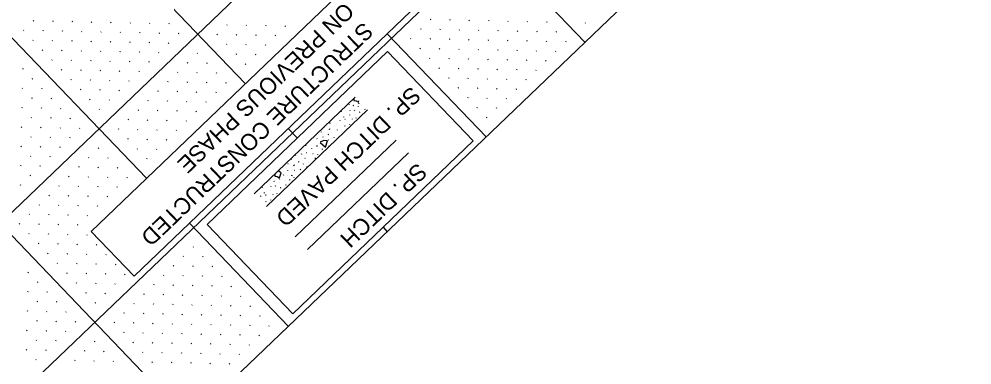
# Model space of a CAD drawing. Extents: x 2148987 to 2151117, y 142806 to 144993.
# Drawn here: x 2149870.3 to 2150218.3, y 143765.8 to 143892.2 of the extents above; entities that cross this region are included whole.
import ezdxf

# ---------------------------------------------------------------- set-up
doc = ezdxf.new("R2010")
doc.units = 0
for name, color, linetype in [('PR_Grading_Txt', 7, 'Continuous'), ('PR_Misc_Improvement', 7, 'Continuous'), ('PR_PIER_PH3', 7, 'Continuous'), ('PR_Road_Concrete', 7, 'Continuous'), ('PR_Storm_Ditch_Paved', 7, 'Continuous'), ('PR_Storm_Ditch_Special', 7, 'Continuous'), ('SHT_Profile_Grid_Minor', 7, 'Continuous')]:
    doc.layers.add(name, color=color, linetype=linetype)

msp = doc.modelspace()

# ---------------------------------------------------------------- linework, layer by layer
at = {"layer": 'PR_Misc_Improvement'}
for points in [[(2150024.95, 143906.21), (2149912.27, 143798.22), (2149896.58, 143814.59), (2150009.26, 143922.58)], [(2150036.16, 143847.7), (2149970.24, 143784.53), (2149938.95, 143817.18), (2150004.87, 143880.35)]]:
    msp.add_lwpolyline(points, close=True, dxfattribs=at)
at = {"layer": 'PR_PIER_PH3'}
for p, q in [((2150504.13, 144431.57), (2149367, 143341.82)), ((2150538.73, 144395.47), (2149401.59, 143305.72)), ((2149731, 144244.68), (2150076.96, 143883.69)), ((2149658.8, 144175.49), (2149952.92, 143868.59)), ((2149622.71, 144140.89), (2149916.82, 143833.99)), ((2149622.71, 144140.89), (2149916.82, 143833.99)), ((2149586.61, 144106.3), (2149932.56, 143745.3)), ((2150004.71, 143886.81), (2150040.86, 143849.09)), ((2149968.61, 143852.22), (2149971.91, 143848.77)), ((2149932.51, 143817.62), (2149968.66, 143779.9)), ((2149932.51, 143817.62), (2149968.66, 143779.9)), ((2150003.2, 143816.12), (2150004.76, 143814.49))]:
    msp.add_line(p, q, dxfattribs=at)
at = {"layer": 'PR_Road_Concrete'}
msp.add_line((2150573.32, 144359.37), (2149436.19, 143269.62), dxfattribs=at)
at = {"layer": 'PR_Storm_Ditch_Paved'}
for p, q in [((2149992.57, 143862.54), (2149992.42, 143862.55)), ((2149987.92, 143858.46), (2149987.92, 143858.31)), ((2149989.35, 143860.14), (2149989.33, 143860.16)), ((2149990.95, 143860.84), (2149990.95, 143860.92)), ((2149991.14, 143858.82), (2149991.14, 143858.67)), ((2149992.49, 143860.42), (2149992.34, 143860.65)), ((2149992.92, 143858.63), (2149992.77, 143858.86)), ((2149994.22, 143860.11), (2149994.23, 143860.19)), ((2149994.44, 143861.23), (2149994.29, 143861.46)), ((2149996.72, 143859.01), (2149996.57, 143859.25)), ((2149986.26, 143856.8), (2149986.26, 143856.87)), ((2149987.39, 143855.22), (2149987.38, 143855.07)), ((2149988.73, 143856.43), (2149988.73, 143856.28)), ((2149989.37, 143855.53), (2149989.21, 143855.53)), ((2149991.14, 143857.08), (2149991.14, 143857.16)), ((2149991.89, 143855.75), (2149991.89, 143855.59)), ((2149993.4, 143855.99), (2149993.4, 143856.06)), ((2149994.72, 143858.16), (2149994.53, 143858.05)), ((2149995.32, 143857.07), (2149995.32, 143856.91)), ((2149981.91, 143852.63), (2149981.72, 143852.75)), ((2149983.68, 143852.13), (2149983.52, 143851.74)), ((2149983.8, 143854.22), (2149983.8, 143854.06)), ((2149986.39, 143853.74), (2149986.39, 143853.81)), ((2149986.42, 143851.72), (2149986.42, 143851.57)), ((2149989.39, 143852.98), (2149989.24, 143853.21)), ((2149991.07, 143853.67), (2149991.07, 143853.75)), ((2149979.15, 143848.39), (2149979, 143848.55)), ((2149979.23, 143850.36), (2149979.11, 143850.37)), ((2149980.79, 143850.87), (2149980.79, 143850.95)), ((2149981.26, 143849.12), (2149981.25, 143848.97)), ((2149983.44, 143849.93), (2149983.17, 143849.97)), ((2149983.32, 143847.92), (2149983.17, 143847.92)), ((2149985.32, 143848.92), (2149985.32, 143849)), ((2149987.96, 143851.07), (2149987.96, 143851.15)), ((2149974.88, 143846.05), (2149974.88, 143845.89)), ((2149977.1, 143844.91), (2149977.06, 143844.8)), ((2149978.87, 143845.84), (2149979.25, 143845.84)), ((2149981.01, 143844.72), (2149981.01, 143844.56)), ((2149983.46, 143845.63), (2149983.31, 143845.63)), ((2149969.78, 143840.85), (2149969.62, 143840.85)), ((2149971.4, 143842.48), (2149971.21, 143842.37)), ((2149973.54, 143842.71), (2149973.39, 143842.94)), ((2149974.82, 143841.21), (2149974.66, 143841.21)), ((2149975.36, 143843.25), (2149975.21, 143843.25)), ((2149977.69, 143842.98), (2149977.61, 143842.99)), ((2149978.61, 143841.28), (2149978.34, 143841.25)), ((2149979.38, 143842.62), (2149979.38, 143842.7)), ((2149968.58, 143839.33), (2149968.43, 143839.33)), ((2149970.5, 143838.59), (2149970.82, 143838.89)), ((2149972.32, 143840.1), (2149972.31, 143839.95)), ((2149974.04, 143839.33), (2149974.04, 143839.17)), ((2149975.45, 143838.02), (2149975.29, 143838.02)), ((2149976.02, 143839.64), (2149976.02, 143839.71)), ((2149963.69, 143834.87), (2149963.54, 143834.87)), ((2149966.99, 143835.07), (2149966.84, 143835.3)), ((2149968.23, 143835.12), (2149968.23, 143835.19)), ((2149968.3, 143837.01), (2149968.3, 143836.86)), ((2149969.92, 143834.85), (2149969.97, 143835.27)), ((2149970.85, 143836.8), (2149970.7, 143836.81)), ((2149970.8, 143834.17), (2149970.8, 143834.25)), ((2149973.14, 143837.1), (2149972.95, 143837.3)), ((2149959.04, 143830.79), (2149959.04, 143830.63)), ((2149960.47, 143832.46), (2149960.45, 143832.49)), ((2149962.07, 143833.16), (2149962.07, 143833.24)), ((2149962.26, 143831.15), (2149962.26, 143830.99)), ((2149963.61, 143832.74), (2149963.46, 143832.97)), ((2149964.04, 143830.95), (2149963.89, 143831.19)), ((2149965.35, 143832.43), (2149965.35, 143832.51)), ((2149965.56, 143833.55), (2149965.41, 143833.78)), ((2149965.84, 143830.49), (2149965.65, 143830.38)), ((2149967.64, 143833.27), (2149967.64, 143833.35)), ((2149967.84, 143831.34), (2149967.69, 143831.57)), ((2149969.08, 143833.51), (2149969.08, 143833.36)), ((2149957.38, 143829.12), (2149957.38, 143829.2)), ((2149958.51, 143827.55), (2149958.5, 143827.39)), ((2149959.85, 143828.76), (2149959.85, 143828.6)), ((2149960.49, 143827.85), (2149960.33, 143827.86)), ((2149962.26, 143829.4), (2149962.26, 143829.48)), ((2149963.01, 143828.07), (2149963.01, 143827.92)), ((2149964.52, 143828.31), (2149964.52, 143828.39)), ((2149966.44, 143829.39), (2149966.44, 143829.24)), ((2149960.51, 143825.3), (2149960.36, 143825.53)), ((2149962.19, 143826), (2149962.19, 143826.08))]:
    msp.add_line(p, q, dxfattribs=at)
for points in [[(2149992.59, 143863.28), (2149992.58, 143862.45), (2149993.4, 143862.28), (2149994.21, 143861.81), (2149994.36, 143862.25)], [(2149980.31, 143847.14), (2149982.21, 143845.41), (2149982.97, 143847.72), (2149981.64, 143847.79), (2149980.31, 143847.17)], [(2149963.71, 143835.61), (2149963.7, 143834.78), (2149964.52, 143834.6), (2149965.33, 143834.13), (2149965.48, 143834.58)], [(2149965.48, 143834.58), (2149965.98, 143836.04), (2149964.97, 143836.75), (2149964.87, 143836.72)]]:
    msp.add_lwpolyline(points, dxfattribs=at)
at = {"layer": 'PR_Storm_Ditch_Special'}
for p, q in [((2149993, 143863.68), (2149956.12, 143828.34)), ((2149997.49, 143858.99), (2149960.61, 143823.65)), ((2150008.05, 143847.97), (2149971.17, 143812.63)), ((2150012.54, 143843.29), (2149975.66, 143807.95))]:
    msp.add_line(p, q, dxfattribs=at)
at = {"layer": 'SHT_Profile_Grid_Minor'}
for p, q in [((2149875.64, 143891.59), (2149875.46, 143891.42)), ((2149882.71, 143891.44), (2149882.53, 143891.27)), ((2149889.78, 143891.29), (2149889.6, 143891.12)), ((2149896.85, 143891.14), (2149896.67, 143890.97)), ((2149903.92, 143890.99), (2149903.74, 143890.82)), ((2149910.99, 143890.84), (2149910.81, 143890.67)), ((2149918.06, 143890.69), (2149917.88, 143890.52)), ((2149925.13, 143890.54), (2149924.95, 143890.37)), ((2149946.34, 143890.09), (2149946.15, 143889.92)), ((2149953.4, 143889.94), (2149953.22, 143889.77)), ((2149960.47, 143889.79), (2149960.29, 143889.62)), ((2149967.54, 143889.64), (2149967.36, 143889.47)), ((2150020.64, 143892.04), (2150020.46, 143891.87)), ((2150027.71, 143891.89), (2150027.53, 143891.72)), ((2150034.78, 143891.74), (2150034.6, 143891.57)), ((2150041.85, 143891.59), (2150041.67, 143891.42)), ((2150048.92, 143891.44), (2150048.74, 143891.27)), ((2150055.99, 143891.29), (2150055.81, 143891.12)), ((2150063.06, 143891.14), (2150062.88, 143890.97)), ((2150077.2, 143890.84), (2150077.02, 143890.67)), ((2149872.03, 143888.13), (2149871.85, 143887.96)), ((2149879.1, 143887.98), (2149878.92, 143887.81)), ((2149886.17, 143887.83), (2149885.99, 143887.66)), ((2149893.24, 143887.68), (2149893.06, 143887.51)), ((2149900.31, 143887.53), (2149900.13, 143887.36)), ((2149907.38, 143887.38), (2149907.2, 143887.21)), ((2149914.45, 143887.23), (2149914.27, 143887.06)), ((2149921.52, 143887.08), (2149921.34, 143886.91)), ((2149928.59, 143886.93), (2149928.41, 143886.76)), ((2149942.73, 143886.63), (2149942.54, 143886.46)), ((2149949.79, 143886.48), (2149949.61, 143886.31)), ((2149956.86, 143886.33), (2149956.68, 143886.16)), ((2149963.93, 143886.18), (2149963.75, 143886.01)), ((2150017.03, 143888.59), (2150016.85, 143888.41)), ((2150024.1, 143888.43), (2150023.92, 143888.26)), ((2150031.17, 143888.28), (2150030.99, 143888.11)), ((2150038.24, 143888.13), (2150038.06, 143887.96)), ((2150045.31, 143887.98), (2150045.13, 143887.81)), ((2150052.38, 143887.83), (2150052.2, 143887.66)), ((2150059.45, 143887.68), (2150059.27, 143887.51)), ((2150066.52, 143887.53), (2150066.34, 143887.36)), ((2149875.49, 143884.52), (2149875.31, 143884.35)), ((2149882.56, 143884.37), (2149882.38, 143884.2)), ((2149889.63, 143884.22), (2149889.45, 143884.05)), ((2149896.7, 143884.07), (2149896.52, 143883.9)), ((2149903.77, 143883.92), (2149903.59, 143883.75)), ((2149910.84, 143883.77), (2149910.66, 143883.6)), ((2149917.91, 143883.62), (2149917.73, 143883.45)), ((2149924.98, 143883.47), (2149924.8, 143883.3)), ((2149946.18, 143883.02), (2149946, 143882.85)), ((2149953.25, 143882.87), (2149953.07, 143882.7)), ((2149960.32, 143882.72), (2149960.14, 143882.55)), ((2150013.42, 143885.13), (2150013.24, 143884.95)), ((2150020.49, 143884.98), (2150020.31, 143884.8)), ((2150027.56, 143884.82), (2150027.38, 143884.65)), ((2150034.63, 143884.67), (2150034.45, 143884.5)), ((2150041.7, 143884.52), (2150041.52, 143884.35)), ((2150048.77, 143884.37), (2150048.59, 143884.2)), ((2150055.84, 143884.22), (2150055.66, 143884.05)), ((2150062.91, 143884.07), (2150062.73, 143883.9)), ((2150069.98, 143883.92), (2150069.8, 143883.75)), ((2149878.95, 143880.91), (2149878.77, 143880.74)), ((2149886.02, 143880.76), (2149885.84, 143880.59)), ((2149893.09, 143880.61), (2149892.91, 143880.44)), ((2149900.16, 143880.46), (2149899.98, 143880.29)), ((2149907.23, 143880.31), (2149907.05, 143880.14)), ((2149914.3, 143880.16), (2149914.12, 143879.99)), ((2149921.37, 143880.01), (2149921.19, 143879.84)), ((2149935.51, 143879.71), (2149935.32, 143879.54)), ((2149949.64, 143879.41), (2149949.46, 143879.24)), ((2149956.71, 143879.26), (2149956.53, 143879.09)), ((2150016.88, 143881.52), (2150016.7, 143881.34)), ((2150023.95, 143881.37), (2150023.77, 143881.19)), ((2150031.02, 143881.21), (2150030.84, 143881.04)), ((2150038.09, 143881.06), (2150037.91, 143880.89)), ((2150045.16, 143880.91), (2150044.98, 143880.74)), ((2150052.23, 143880.76), (2150052.05, 143880.59)), ((2150059.3, 143880.61), (2150059.12, 143880.44)), ((2150066.37, 143880.46), (2150066.19, 143880.29)), ((2149882.41, 143877.3), (2149882.23, 143877.13)), ((2149889.48, 143877.15), (2149889.3, 143876.98)), ((2149896.55, 143877), (2149896.37, 143876.83)), ((2149903.62, 143876.85), (2149903.44, 143876.68)), ((2149910.69, 143876.7), (2149910.51, 143876.53)), ((2149917.76, 143876.55), (2149917.58, 143876.38)), ((2149931.9, 143876.25), (2149931.72, 143876.08)), ((2149938.97, 143876.1), (2149938.78, 143875.93)), ((2149953.1, 143875.8), (2149952.92, 143875.63)), ((2150020.34, 143877.91), (2150020.16, 143877.73)), ((2150027.41, 143877.76), (2150027.23, 143877.58)), ((2150034.48, 143877.6), (2150034.3, 143877.43)), ((2150041.55, 143877.45), (2150041.37, 143877.28)), ((2150048.62, 143877.3), (2150048.44, 143877.13)), ((2150055.69, 143877.15), (2150055.51, 143876.98)), ((2150062.76, 143877), (2150062.58, 143876.83)), ((2149871.73, 143874), (2149871.55, 143873.82)), ((2149885.87, 143873.69), (2149885.69, 143873.52)), ((2149892.94, 143873.54), (2149892.76, 143873.37)), ((2149900.01, 143873.39), (2149899.83, 143873.22)), ((2149907.08, 143873.24), (2149906.9, 143873.07)), ((2149914.15, 143873.09), (2149913.97, 143872.92)), ((2149928.29, 143872.79), (2149928.11, 143872.62)), ((2149935.36, 143872.64), (2149935.17, 143872.47)), ((2149942.42, 143872.49), (2149942.24, 143872.32)), ((2150023.8, 143874.3), (2150023.62, 143874.12)), ((2150030.87, 143874.15), (2150030.69, 143873.97)), ((2150037.94, 143873.99), (2150037.76, 143873.82)), ((2150045.01, 143873.84), (2150044.83, 143873.67)), ((2150052.08, 143873.69), (2150051.9, 143873.52)), ((2150059.15, 143873.54), (2150058.97, 143873.37)), ((2149875.19, 143870.39), (2149875.01, 143870.21)), ((2149889.33, 143870.08), (2149889.15, 143869.91)), ((2149896.4, 143869.93), (2149896.22, 143869.76)), ((2149903.47, 143869.78), (2149903.29, 143869.61)), ((2149910.54, 143869.63), (2149910.36, 143869.46)), ((2149924.68, 143869.33), (2149924.5, 143869.16)), ((2149931.75, 143869.18), (2149931.56, 143869.01)), ((2149938.81, 143869.03), (2149938.63, 143868.86)), ((2149945.88, 143868.88), (2149945.7, 143868.71)), ((2150027.26, 143870.69), (2150027.08, 143870.51)), ((2150034.33, 143870.54), (2150034.15, 143870.36)), ((2150041.4, 143870.38), (2150041.22, 143870.21)), ((2150048.47, 143870.23), (2150048.29, 143870.06)), ((2150055.54, 143870.08), (2150055.36, 143869.91)), ((2149871.58, 143866.93), (2149871.4, 143866.75)), ((2149878.65, 143866.78), (2149878.47, 143866.6)), ((2149892.79, 143866.47), (2149892.61, 143866.3)), ((2149899.86, 143866.32), (2149899.68, 143866.15)), ((2149906.93, 143866.17), (2149906.75, 143866)), ((2149921.07, 143865.87), (2149920.89, 143865.7)), ((2149928.14, 143865.72), (2149927.95, 143865.55)), ((2149935.2, 143865.57), (2149935.02, 143865.4)), ((2149942.27, 143865.42), (2149942.09, 143865.25)), ((2150030.72, 143867.08), (2150030.54, 143866.9)), ((2150037.79, 143866.93), (2150037.61, 143866.75)), ((2150044.86, 143866.78), (2150044.68, 143866.6)), ((2150051.93, 143866.62), (2150051.75, 143866.45)), ((2149875.04, 143863.32), (2149874.86, 143863.14)), ((2149882.11, 143863.17), (2149881.93, 143862.99)), ((2149896.25, 143862.86), (2149896.07, 143862.69)), ((2149903.32, 143862.71), (2149903.14, 143862.54)), ((2149917.46, 143862.41), (2149917.28, 143862.24)), ((2149924.53, 143862.26), (2149924.34, 143862.09)), ((2149931.59, 143862.11), (2149931.41, 143861.94)), ((2149938.66, 143861.96), (2149938.48, 143861.79)), ((2150034.18, 143863.47), (2150034, 143863.29)), ((2150041.25, 143863.32), (2150041.07, 143863.14)), ((2150048.32, 143863.17), (2150048.14, 143862.99)), ((2149871.43, 143859.86), (2149871.25, 143859.68)), ((2149878.5, 143859.71), (2149878.32, 143859.53)), ((2149885.57, 143859.56), (2149885.39, 143859.38)), ((2149899.71, 143859.25), (2149899.53, 143859.08)), ((2149913.85, 143858.95), (2149913.67, 143858.78)), ((2149920.92, 143858.8), (2149920.73, 143858.63)), ((2149927.98, 143858.65), (2149927.8, 143858.48)), ((2149935.05, 143858.5), (2149934.87, 143858.33)), ((2150037.64, 143859.86), (2150037.46, 143859.68)), ((2150044.71, 143859.71), (2150044.53, 143859.53)), ((2149874.89, 143856.25), (2149874.71, 143856.07)), ((2149881.96, 143856.1), (2149881.78, 143855.92)), ((2149889.03, 143855.95), (2149888.85, 143855.77)), ((2149910.24, 143855.49), (2149910.06, 143855.32)), ((2149917.31, 143855.34), (2149917.12, 143855.17)), ((2149924.37, 143855.19), (2149924.19, 143855.02)), ((2149931.44, 143855.04), (2149931.26, 143854.87)), ((2150041.1, 143856.25), (2150040.92, 143856.07)), ((2149871.28, 143852.79), (2149871.1, 143852.61)), ((2149878.35, 143852.64), (2149878.17, 143852.46)), ((2149885.42, 143852.49), (2149885.24, 143852.31)), ((2149892.49, 143852.34), (2149892.31, 143852.16)), ((2149906.63, 143852.03), (2149906.45, 143851.86)), ((2149913.7, 143851.88), (2149913.51, 143851.71)), ((2149920.76, 143851.73), (2149920.58, 143851.56)), ((2149927.83, 143851.58), (2149927.65, 143851.41)), ((2149874.74, 143849.18), (2149874.56, 143849)), ((2149881.81, 143849.03), (2149881.63, 143848.85)), ((2149888.88, 143848.88), (2149888.7, 143848.7)), ((2149910.09, 143848.42), (2149909.9, 143848.25)), ((2149917.15, 143848.27), (2149916.97, 143848.1)), ((2149924.22, 143848.12), (2149924.04, 143847.95)), ((2149871.13, 143845.72), (2149870.95, 143845.54)), ((2149878.2, 143845.57), (2149878.02, 143845.39)), ((2149885.27, 143845.42), (2149885.09, 143845.24)), ((2149899.41, 143845.12), (2149899.23, 143844.94)), ((2149913.54, 143844.81), (2149913.36, 143844.64)), ((2149920.61, 143844.66), (2149920.43, 143844.49)), ((2149874.59, 143842.11), (2149874.41, 143841.93)), ((2149881.66, 143841.96), (2149881.48, 143841.78)), ((2149895.8, 143841.66), (2149895.62, 143841.48)), ((2149902.87, 143841.51), (2149902.68, 143841.33)), ((2149917, 143841.2), (2149916.82, 143841.03)), ((2149870.98, 143838.65), (2149870.8, 143838.48)), ((2149878.05, 143838.5), (2149877.87, 143838.32)), ((2149892.19, 143838.2), (2149892.01, 143838.02)), ((2149899.26, 143838.05), (2149899.08, 143837.87)), ((2149906.32, 143837.9), (2149906.14, 143837.72)), ((2149874.44, 143835.04), (2149874.26, 143834.87)), ((2149888.58, 143834.74), (2149888.4, 143834.56)), ((2149895.65, 143834.59), (2149895.47, 143834.41)), ((2149902.72, 143834.44), (2149902.53, 143834.26)), ((2149909.78, 143834.29), (2149909.6, 143834.11)), ((2149870.83, 143831.58), (2149870.65, 143831.41)), ((2149884.97, 143831.28), (2149884.79, 143831.1)), ((2149892.04, 143831.13), (2149891.86, 143830.95)), ((2149899.11, 143830.98), (2149898.92, 143830.8)), ((2149906.17, 143830.83), (2149905.99, 143830.65)), ((2149881.36, 143827.82), (2149881.18, 143827.65)), ((2149888.43, 143827.67), (2149888.25, 143827.49)), ((2149895.5, 143827.52), (2149895.31, 143827.34)), ((2149902.56, 143827.37), (2149902.38, 143827.19)), ((2149877.75, 143824.36), (2149877.57, 143824.19)), ((2149884.82, 143824.21), (2149884.64, 143824.04)), ((2149891.89, 143824.06), (2149891.7, 143823.88)), ((2149898.95, 143823.91), (2149898.77, 143823.73)), ((2149874.14, 143820.9), (2149873.96, 143820.73)), ((2149881.21, 143820.75), (2149881.03, 143820.58)), ((2149888.28, 143820.6), (2149888.09, 143820.43)), ((2149895.34, 143820.45), (2149895.16, 143820.27)), ((2149870.53, 143817.44), (2149870.35, 143817.27)), ((2149877.6, 143817.29), (2149877.42, 143817.12)), ((2149884.67, 143817.14), (2149884.48, 143816.97)), ((2149891.73, 143816.99), (2149891.55, 143816.82)), ((2149873.99, 143813.83), (2149873.81, 143813.66)), ((2149881.06, 143813.68), (2149880.87, 143813.51)), ((2149888.12, 143813.53), (2149887.94, 143813.36)), ((2149895.19, 143813.38), (2149895.01, 143813.21)), ((2149877.45, 143810.22), (2149877.26, 143810.05)), ((2149884.51, 143810.07), (2149884.33, 143809.9)), ((2149891.58, 143809.92), (2149891.4, 143809.75)), ((2149898.65, 143809.77), (2149898.47, 143809.6)), ((2149880.9, 143806.61), (2149880.72, 143806.44)), ((2149887.97, 143806.46), (2149887.79, 143806.29)), ((2149895.04, 143806.31), (2149894.86, 143806.14)), ((2149902.11, 143806.16), (2149901.93, 143805.99)), ((2149934, 143809.02), (2149933.82, 143808.84)), ((2149884.36, 143803), (2149884.18, 143802.83)), ((2149891.43, 143802.85), (2149891.25, 143802.68)), ((2149898.5, 143802.7), (2149898.32, 143802.53)), ((2149905.57, 143802.55), (2149905.39, 143802.38)), ((2149930.39, 143805.56), (2149930.21, 143805.38)), ((2149937.46, 143805.41), (2149937.28, 143805.23)), ((2149873.68, 143799.69), (2149873.5, 143799.52)), ((2149887.82, 143799.39), (2149887.64, 143799.22)), ((2149894.89, 143799.24), (2149894.71, 143799.07)), ((2149901.96, 143799.09), (2149901.78, 143798.92)), ((2149926.78, 143802.1), (2149926.6, 143801.92)), ((2149933.85, 143801.95), (2149933.67, 143801.77)), ((2149940.92, 143801.8), (2149940.74, 143801.62)), ((2149877.14, 143796.08), (2149876.96, 143795.91)), ((2149891.28, 143795.78), (2149891.1, 143795.61)), ((2149898.35, 143795.63), (2149898.17, 143795.46)), ((2149909.03, 143798.94), (2149908.85, 143798.77)), ((2149923.17, 143798.64), (2149922.99, 143798.46)), ((2149930.24, 143798.49), (2149930.06, 143798.31)), ((2149937.31, 143798.34), (2149937.13, 143798.16)), ((2149944.38, 143798.19), (2149944.2, 143798.01)), ((2149873.53, 143792.62), (2149873.35, 143792.45)), ((2149880.6, 143792.47), (2149880.42, 143792.3)), ((2149894.74, 143792.17), (2149894.56, 143792)), ((2149905.42, 143795.48), (2149905.24, 143795.31)), ((2149919.56, 143795.18), (2149919.38, 143795.01)), ((2149926.63, 143795.03), (2149926.45, 143794.85)), ((2149933.7, 143794.88), (2149933.52, 143794.7)), ((2149940.77, 143794.73), (2149940.59, 143794.55)), ((2149947.84, 143794.58), (2149947.66, 143794.4)), ((2149876.99, 143789.01), (2149876.81, 143788.84)), ((2149884.06, 143788.86), (2149883.88, 143788.69)), ((2149901.81, 143792.02), (2149901.63, 143791.85)), ((2149915.95, 143791.72), (2149915.77, 143791.55)), ((2149923.02, 143791.57), (2149922.84, 143791.4)), ((2149930.09, 143791.42), (2149929.91, 143791.24)), ((2149937.16, 143791.27), (2149936.98, 143791.09)), ((2149944.23, 143791.12), (2149944.05, 143790.94)), ((2149951.3, 143790.97), (2149951.12, 143790.79)), ((2149873.38, 143785.55), (2149873.2, 143785.38)), ((2149880.45, 143785.4), (2149880.27, 143785.23)), ((2149887.52, 143785.25), (2149887.34, 143785.08)), ((2149898.2, 143788.56), (2149898.02, 143788.39)), ((2149912.34, 143788.26), (2149912.16, 143788.09)), ((2149919.41, 143788.11), (2149919.23, 143787.94)), ((2149926.48, 143787.96), (2149926.3, 143787.79)), ((2149933.55, 143787.81), (2149933.37, 143787.63)), ((2149940.62, 143787.66), (2149940.44, 143787.48)), ((2149947.69, 143787.51), (2149947.51, 143787.33)), ((2149954.76, 143787.36), (2149954.58, 143787.18)), ((2149876.84, 143781.94), (2149876.66, 143781.77)), ((2149883.91, 143781.79), (2149883.73, 143781.62)), ((2149890.98, 143781.64), (2149890.8, 143781.47)), ((2149908.73, 143784.8), (2149908.55, 143784.63)), ((2149915.8, 143784.65), (2149915.62, 143784.48)), ((2149922.87, 143784.5), (2149922.69, 143784.33)), ((2149929.94, 143784.35), (2149929.76, 143784.18)), ((2149937.01, 143784.2), (2149936.83, 143784.02)), ((2149944.08, 143784.05), (2149943.9, 143783.87)), ((2149951.15, 143783.9), (2149950.97, 143783.72)), ((2149958.22, 143783.75), (2149958.04, 143783.57)), ((2149873.23, 143778.48), (2149873.05, 143778.31)), ((2149880.3, 143778.33), (2149880.12, 143778.16)), ((2149887.37, 143778.18), (2149887.19, 143778.01)), ((2149905.12, 143781.34), (2149904.94, 143781.17)), ((2149912.19, 143781.19), (2149912.01, 143781.02)), ((2149919.26, 143781.04), (2149919.08, 143780.87)), ((2149926.33, 143780.89), (2149926.15, 143780.72)), ((2149933.4, 143780.74), (2149933.22, 143780.57)), ((2149940.47, 143780.59), (2149940.29, 143780.41)), ((2149947.54, 143780.44), (2149947.36, 143780.26)), ((2149954.61, 143780.29), (2149954.43, 143780.11)), ((2149961.68, 143780.14), (2149961.5, 143779.96)), ((2149876.69, 143774.87), (2149876.51, 143774.7)), ((2149883.76, 143774.72), (2149883.58, 143774.55)), ((2149908.58, 143777.73), (2149908.4, 143777.56)), ((2149915.65, 143777.58), (2149915.47, 143777.41)), ((2149922.72, 143777.43), (2149922.54, 143777.26)), ((2149929.79, 143777.28), (2149929.61, 143777.11)), ((2149936.86, 143777.13), (2149936.68, 143776.96)), ((2149943.93, 143776.98), (2149943.75, 143776.81)), ((2149951, 143776.83), (2149950.82, 143776.65)), ((2149958.07, 143776.68), (2149957.89, 143776.5)), ((2149873.08, 143771.41), (2149872.9, 143771.24)), ((2149880.15, 143771.26), (2149879.97, 143771.09)), ((2149897.9, 143774.42), (2149897.72, 143774.25)), ((2149912.04, 143774.12), (2149911.86, 143773.95)), ((2149919.11, 143773.97), (2149918.93, 143773.8)), ((2149926.18, 143773.82), (2149926, 143773.65)), ((2149933.25, 143773.67), (2149933.07, 143773.5)), ((2149940.32, 143773.52), (2149940.14, 143773.35)), ((2149947.39, 143773.37), (2149947.21, 143773.2)), ((2149954.46, 143773.22), (2149954.28, 143773.04)), ((2149876.54, 143767.8), (2149876.36, 143767.63)), ((2149894.29, 143770.96), (2149894.11, 143770.79)), ((2149901.36, 143770.81), (2149901.18, 143770.64)), ((2149915.5, 143770.51), (2149915.32, 143770.34)), ((2149922.57, 143770.36), (2149922.39, 143770.19)), ((2149929.64, 143770.21), (2149929.46, 143770.04)), ((2149936.71, 143770.06), (2149936.53, 143769.89)), ((2149943.78, 143769.91), (2149943.6, 143769.74)), ((2149950.85, 143769.76), (2149950.67, 143769.59)), ((2149890.68, 143767.5), (2149890.5, 143767.33)), ((2149897.75, 143767.35), (2149897.57, 143767.18)), ((2149904.82, 143767.2), (2149904.64, 143767.03)), ((2149918.96, 143766.9), (2149918.78, 143766.73)), ((2149926.03, 143766.75), (2149925.85, 143766.58)), ((2149933.1, 143766.6), (2149932.92, 143766.43)), ((2149940.17, 143766.45), (2149939.99, 143766.28)), ((2149947.24, 143766.3), (2149947.06, 143766.13))]:
    msp.add_line(p, q, dxfattribs=at)

# ---------------------------------------------------------------- texts
at = {"layer": 'PR_Grading_Txt'}
for s, p in [('ON PREVIOUS PHASE', (2149989.09, 143898.65)), ('STRUCTURE CONSTRUCTED', (2149996.02, 143891.41)), ('SP. DITCH PAVED', (2150013.43, 143867.93)), ('SP. DITCH', (2150015.72, 143839.99))]:
    msp.add_text(s, height=6, rotation=223.7809, dxfattribs=at).set_placement(p)

doc.saveas('drawing.dxf')
